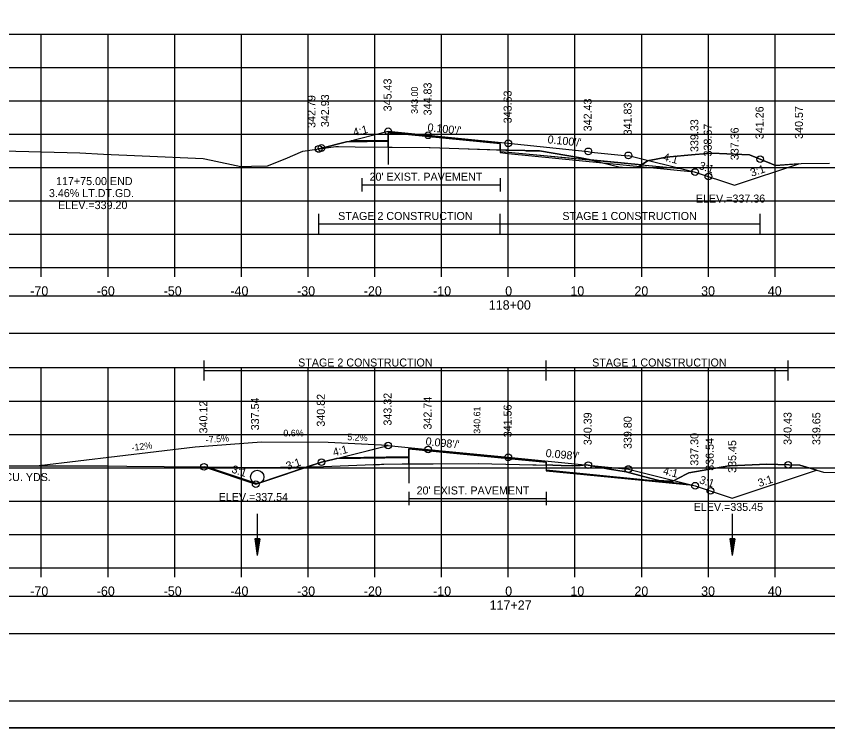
# Model space of a CAD drawing. Extents: x 1376273 to 1384221, y 378927 to 384592.
# Drawn here: x 1376984 to 1377105.7, y 380111.8 to 380218.5 of the extents above; entities that cross this region are included whole.
import ezdxf

# ---------------------------------------------------------------- set-up
doc = ezdxf.new("R2010")
doc.units = 0
for name, color, linetype in [('R_Alt Surface', 7, 'Continuous'), ('R_Axis', 7, 'Continuous'), ('R_Axis Annot', 7, 'Continuous'), ('R_Border', 7, 'Continuous'), ('R_Border Notes', 7, 'Continuous'), ('R_Dimension', 7, 'Continuous'), ('R_Drive', 7, 'Continuous'), ('R_Exist Surface', 7, 'Continuous'), ('R_Fin Surface', 7, 'Continuous'), ('R_Grid', 7, 'Continuous'), ('R_No Plot', 7, 'Continuous'), ('R_Water', 7, 'Continuous'), ('R_Xsect Elev', 7, 'Continuous'), ('R_Xsect Slope', 7, 'Continuous'), ('T_Detection Zones', 7, 'Continuous'), ('T_Notes', 7, 'Continuous'), ('T_Vehicle Path Lt Minor', 7, 'Continuous')]:
    doc.layers.add(name, color=color, linetype=linetype)

msp = doc.modelspace()

# ---------------------------------------------------------------- linework, layer by layer
at = {"layer": 'R_Alt Surface'}
for points in [[(1377034.2, 380199.86), (1377039.76, 380199.92), (1377039.77, 380201.08), (1377056.54, 380199.4), (1377056.54, 380198.24), (1377057.77, 380198.12), (1377083.58, 380195.7)], [(1377035.83, 380194.24), (1377035.83, 380192.24)], [(1377035.83, 380193.24), (1377056.54, 380193.24)], [(1377056.54, 380194.24), (1377056.54, 380192.24)], [(1377032.7, 380152.37), (1377042.87, 380152.5), (1377042.88, 380153.67), (1377057.77, 380152.21), (1377063.46, 380151.66), (1377063.47, 380150.49), (1377084.6, 380148.41)], [(1377042.88, 380147.2), (1377042.88, 380145.2)], [(1377063.46, 380147.2), (1377063.46, 380145.2)], [(1377042.88, 380146.2), (1377063.46, 380146.2)]]:
    msp.add_lwpolyline(points, dxfattribs=at)
at = {"layer": 'R_Axis'}
for p, q in [((1376907.77, 380180.82), (1377207.77, 380180.82)), ((1376987.77, 380179.42), (1376987.77, 380180.82)), ((1376997.77, 380179.42), (1376997.77, 380180.82)), ((1377007.77, 380179.42), (1377007.77, 380180.82)), ((1377017.77, 380179.42), (1377017.77, 380180.82)), ((1377027.77, 380179.42), (1377027.77, 380180.82)), ((1377037.77, 380179.42), (1377037.77, 380180.82)), ((1377047.77, 380179.42), (1377047.77, 380180.82)), ((1377057.77, 380179.42), (1377057.77, 380180.82)), ((1377067.77, 380179.42), (1377067.77, 380180.82)), ((1377077.77, 380179.42), (1377077.77, 380180.82)), ((1377087.77, 380179.42), (1377087.77, 380180.82)), ((1377097.77, 380179.42), (1377097.77, 380180.82)), ((1376907.77, 380135.82), (1377207.77, 380135.82)), ((1376987.77, 380134.42), (1376987.77, 380135.82)), ((1376997.77, 380134.42), (1376997.77, 380135.82)), ((1377007.77, 380134.42), (1377007.77, 380135.82)), ((1377017.77, 380134.42), (1377017.77, 380135.82)), ((1377027.77, 380134.42), (1377027.77, 380135.82)), ((1377037.77, 380134.42), (1377037.77, 380135.82)), ((1377047.77, 380134.42), (1377047.77, 380135.82)), ((1377057.77, 380134.42), (1377057.77, 380135.82)), ((1377067.77, 380134.42), (1377067.77, 380135.82)), ((1377077.77, 380134.42), (1377077.77, 380135.82)), ((1377087.77, 380134.42), (1377087.77, 380135.82)), ((1377097.77, 380134.42), (1377097.77, 380135.82))]:
    msp.add_line(p, q, dxfattribs=at)
at = {"layer": 'R_Axis Annot'}
for points in [[(1376907.2, 380171), (1377209.01, 380171), (1377209.01, 380176.52), (1376907.2, 380176.52)], [(1376907.2, 380125.98), (1377209.01, 380125.98), (1377209.01, 380131.5), (1376907.2, 380131.5)]]:
    msp.add_lwpolyline(points, close=True, dxfattribs=at)
at = {"layer": 'R_Border'}
msp.add_line((1377215.95, 380115.82), (1376899.77, 380115.82), dxfattribs=at)
at = {"layer": 'R_Dimension'}
for p, q in [((1377029.35, 380185.86), (1377029.35, 380188.86)), ((1377056.54, 380185.86), (1377056.54, 380188.86)), ((1377095.54, 380185.86), (1377095.54, 380188.86)), ((1377029.35, 380187.36), (1377095.54, 380187.36)), ((1377012.16, 380163.89), (1377012.16, 380166.89)), ((1377063.46, 380163.89), (1377063.46, 380166.89)), ((1377099.74, 380163.89), (1377099.74, 380166.89)), ((1377012.16, 380165.39), (1377099.74, 380165.39))]:
    msp.add_line(p, q, dxfattribs=at)
at = {"layer": 'R_Drive'}
for p, q in [((1377020.78, 380154.66), (1377010.81, 380153.91)), ((1377030.78, 380154.6), (1377020.78, 380154.66)), ((1377039.77, 380154.14), (1377030.78, 380154.6)), ((1377010.81, 380153.91), (1376987.46, 380151.1))]:
    msp.add_line(p, q, dxfattribs=at)
at = {"layer": 'R_Exist Surface'}
for points in [[(1376982.06, 380198.31), (1376993.54, 380198.01), (1376997.08, 380197.85), (1377002.89, 380197.6), (1377012.03, 380197.2), (1377013.25, 380196.95), (1377017.7, 380195.97), (1377019.28, 380196.02), (1377021.67, 380196.08), (1377024.33, 380197.12), (1377026.97, 380198.26), (1377030.82, 380198.83), (1377031.92, 380198.98), (1377032.34, 380198.97), (1377034.83, 380198.92), (1377045.89, 380198.82), (1377045.98, 380198.82), (1377046.06, 380198.81), (1377050.34, 380198.67), (1377057.41, 380198.44), (1377057.54, 380198.44), (1377057.58, 380198.44), (1377060.27, 380198.36), (1377060.47, 380198.35), (1377062.45, 380198.33), (1377068.6, 380197.26), (1377069.58, 380197.09), (1377069.89, 380197.01), (1377074.52, 380195.87), (1377074.89, 380195.86), (1377077.11, 380195.82), (1377077.97, 380196.39), (1377078.63, 380196.84), (1377079.93, 380197.08), (1377081.45, 380197.4), (1377085.77, 380197.8), (1377088.28, 380197.96), (1377092.8, 380197.76), (1377093.94, 380197.72), (1377097.21, 380196.4), (1377097.84, 380196.13), (1377101.66, 380196.41), (1377105.91, 380196.47)], [(1376977.69, 380151.12), (1376997.62, 380151.08), (1377000.57, 380151.06), (1377006.18, 380151), (1377021.89, 380150.85), (1377022.59, 380150.85), (1377023.6, 380150.91), (1377026.07, 380150.89), (1377030.06, 380150.98), (1377037.58, 380151.28), (1377038.46, 380151.32), (1377038.77, 380151.33), (1377038.8, 380151.33), (1377039.14, 380151.34), (1377041.88, 380151.41), (1377046.49, 380151.42), (1377053.28, 380151.43), (1377059.44, 380151.29), (1377064.46, 380151.18), (1377065.71, 380151.15), (1377067.41, 380151.1), (1377068.57, 380151.16), (1377069.48, 380151.23), (1377072.65, 380150.67), (1377075.46, 380150.18), (1377078.97, 380149.24), (1377080.32, 380148.89), (1377081.86, 380148.82), (1377082.44, 380148.8), (1377083.07, 380149.15), (1377084.83, 380150.05), (1377090.82, 380151.08), (1377090.94, 380151.1), (1377091.03, 380151.1), (1377096.53, 380151.37), (1377099.83, 380151.24), (1377101.49, 380151.19), (1377104.51, 380150.31), (1377105.03, 380150.14), (1377109.27, 380150.05)]]:
    msp.add_lwpolyline(points, dxfattribs=at)
at = {"layer": 'R_Fin Surface'}
for points in [[(1377029.35, 380198.61), (1377029.77, 380198.75), (1377033.53, 380199.69), (1377039.77, 380201.25), (1377045.77, 380200.65), (1377057.77, 380199.45), (1377069.77, 380198.25), (1377070.19, 380198.11), (1377075.68, 380197.56), (1377075.77, 380197.65), (1377085.64, 380195.18), (1377085.77, 380195.15), (1377091.7, 380193.17), (1377101.34, 380196.39), (1377101.34, 380196.39), (1377101.34, 380196.39)], [(1377012.16, 380150.94), (1377019.91, 380148.36), (1377029.77, 380151.64), (1377031.67, 380152.11), (1377039.77, 380154.14), (1377045.77, 380153.55), (1377057.77, 380152.38), (1377069.77, 380151.21), (1377075.77, 380150.62), (1377085.77, 380148.12), (1377091.34, 380146.26), (1377103.96, 380150.47)]]:
    msp.add_lwpolyline(points, dxfattribs=at)
at = {"layer": 'R_Grid'}
for p, q in [((1376907.77, 380215.82), (1377207.77, 380215.82)), ((1376907.77, 380215.82), (1377207.77, 380215.82)), ((1376987.77, 380180.82), (1376987.77, 380215.82)), ((1376987.77, 380180.82), (1376987.77, 380215.82)), ((1376997.77, 380180.82), (1376997.77, 380215.82)), ((1376997.77, 380180.82), (1376997.77, 380215.82)), ((1377007.77, 380180.82), (1377007.77, 380215.82)), ((1377007.77, 380180.82), (1377007.77, 380215.82)), ((1377017.77, 380180.82), (1377017.77, 380215.82)), ((1377017.77, 380180.82), (1377017.77, 380215.82)), ((1377027.77, 380180.82), (1377027.77, 380215.82)), ((1377027.77, 380180.82), (1377027.77, 380215.82)), ((1377037.77, 380180.82), (1377037.77, 380215.82)), ((1377037.77, 380180.82), (1377037.77, 380215.82)), ((1377047.77, 380180.82), (1377047.77, 380215.82)), ((1377047.77, 380180.82), (1377047.77, 380215.82)), ((1377057.77, 380180.82), (1377057.77, 380215.82)), ((1377057.77, 380180.82), (1377057.77, 380215.82)), ((1377067.77, 380180.82), (1377067.77, 380215.82)), ((1377067.77, 380180.82), (1377067.77, 380215.82)), ((1377077.77, 380180.82), (1377077.77, 380215.82)), ((1377077.77, 380180.82), (1377077.77, 380215.82)), ((1377087.77, 380180.82), (1377087.77, 380215.82)), ((1377087.77, 380180.82), (1377087.77, 380215.82)), ((1377097.77, 380180.82), (1377097.77, 380215.82)), ((1377097.77, 380180.82), (1377097.77, 380215.82)), ((1376907.77, 380210.82), (1377207.77, 380210.82)), ((1376907.77, 380210.82), (1377207.77, 380210.82)), ((1376907.77, 380205.82), (1377207.77, 380205.82)), ((1376907.77, 380205.82), (1377207.77, 380205.82)), ((1376907.77, 380200.82), (1377207.77, 380200.82)), ((1376907.77, 380200.82), (1377207.77, 380200.82)), ((1376907.77, 380195.82), (1377207.77, 380195.82)), ((1376907.77, 380195.82), (1377207.77, 380195.82)), ((1376907.77, 380190.82), (1377207.77, 380190.82)), ((1376907.77, 380190.82), (1377207.77, 380190.82)), ((1376907.77, 380185.82), (1377207.77, 380185.82)), ((1376907.77, 380185.82), (1377207.77, 380185.82)), ((1376907.77, 380180.82), (1377207.77, 380180.82)), ((1376907.77, 380180.82), (1377207.77, 380180.82)), ((1376907.77, 380165.82), (1377207.77, 380165.82)), ((1376907.77, 380165.82), (1377207.77, 380165.82)), ((1376987.77, 380135.82), (1376987.77, 380165.82)), ((1376987.77, 380135.82), (1376987.77, 380165.82)), ((1376997.77, 380135.82), (1376997.77, 380165.82)), ((1376997.77, 380135.82), (1376997.77, 380165.82)), ((1377007.77, 380135.82), (1377007.77, 380165.82)), ((1377007.77, 380135.82), (1377007.77, 380165.82)), ((1377017.77, 380135.82), (1377017.77, 380165.82)), ((1377017.77, 380135.82), (1377017.77, 380165.82)), ((1377027.77, 380135.82), (1377027.77, 380165.82)), ((1377027.77, 380135.82), (1377027.77, 380165.82)), ((1377037.77, 380135.82), (1377037.77, 380165.82)), ((1377037.77, 380135.82), (1377037.77, 380165.82)), ((1377047.77, 380135.82), (1377047.77, 380165.82)), ((1377047.77, 380135.82), (1377047.77, 380165.82)), ((1377057.77, 380135.82), (1377057.77, 380165.82)), ((1377057.77, 380135.82), (1377057.77, 380165.82)), ((1377067.77, 380135.82), (1377067.77, 380165.82)), ((1377067.77, 380135.82), (1377067.77, 380165.82)), ((1377077.77, 380135.82), (1377077.77, 380165.82)), ((1377077.77, 380135.82), (1377077.77, 380165.82)), ((1377087.77, 380135.82), (1377087.77, 380165.82)), ((1377087.77, 380135.82), (1377087.77, 380165.82)), ((1377097.77, 380135.82), (1377097.77, 380165.82)), ((1377097.77, 380135.82), (1377097.77, 380165.82)), ((1376907.77, 380160.82), (1377207.77, 380160.82)), ((1376907.77, 380160.82), (1377207.77, 380160.82)), ((1376907.77, 380155.82), (1377207.77, 380155.82)), ((1376907.77, 380155.82), (1377207.77, 380155.82)), ((1376907.77, 380150.82), (1377207.77, 380150.82)), ((1376907.77, 380150.82), (1377207.77, 380150.82)), ((1376907.77, 380145.82), (1377207.77, 380145.82)), ((1376907.77, 380145.82), (1377207.77, 380145.82)), ((1376907.77, 380140.82), (1377207.77, 380140.82)), ((1376907.77, 380140.82), (1377207.77, 380140.82)), ((1376907.77, 380135.82), (1377207.77, 380135.82)), ((1376907.77, 380135.82), (1377207.77, 380135.82))]:
    msp.add_line(p, q, dxfattribs=at)
at = {"layer": 'R_No Plot'}
msp.add_line((1376887.37, 380111.84), (1377220.7, 380111.84), dxfattribs=at)
for points in [[(1376887.36, 380325.17), (1377220.7, 380325.17), (1377220.7, 380111.84), (1376887.36, 380111.84)], [(1377133.69, 380321.28), (1377133.69, 380311.4), (1377169.42, 380311.4), (1377169.42, 380308.48), (1377192.62, 380308.48), (1377192.62, 380284.15), (1377215.95, 380284.15), (1377215.95, 380115.82), (1376899.77, 380115.82), (1376899.77, 380321.28)]]:
    msp.add_lwpolyline(points, close=True, dxfattribs=at)
for points in [[(1377033.53, 380199.69), (1377039.76, 380199.75), (1377039.77, 380201.08), (1377056.54, 380199.4), (1377056.54, 380198.07), (1377057.77, 380197.95), (1377085.64, 380195.18)], [(1377032.03, 380152.21), (1377042.87, 380152.34), (1377042.88, 380153.67), (1377057.77, 380152.21), (1377063.46, 380151.66), (1377063.47, 380150.33), (1377085.51, 380148.19)]]:
    msp.add_lwpolyline(points, dxfattribs=at)
for centre in [(1377039.77, 380201.25), (1377039.77, 380201.25), (1377045.77, 380200.65), (1377045.77, 380200.65), (1377029.77, 380198.75), (1377029.77, 380198.75), (1377057.77, 380199.45), (1377057.77, 380199.45), (1377029.35, 380198.61), (1377029.35, 380198.61), (1377069.77, 380198.25), (1377069.77, 380198.25), (1377075.77, 380197.65), (1377075.77, 380197.65), (1377095.54, 380197.08), (1377095.54, 380197.08), (1377085.77, 380195.15), (1377085.77, 380195.15), (1377087.77, 380194.48), (1377087.77, 380194.48), (1377087.77, 380194.48), (1377087.77, 380194.48), (1377039.77, 380154.14), (1377039.77, 380154.14), (1377045.77, 380153.55), (1377045.77, 380153.55), (1377029.77, 380151.64), (1377029.77, 380151.64), (1377057.77, 380152.38), (1377057.77, 380152.38), (1377069.77, 380151.21), (1377069.77, 380151.21), (1377099.74, 380151.25), (1377099.74, 380151.25), (1377012.16, 380150.94), (1377012.16, 380150.94), (1377075.77, 380150.62), (1377075.77, 380150.62), (1377019.91, 380148.36), (1377019.91, 380148.36), (1377019.91, 380148.36), (1377019.91, 380148.36), (1377085.77, 380148.12), (1377085.77, 380148.12), (1377088.07, 380147.36), (1377088.07, 380147.36), (1377088.07, 380147.36), (1377088.07, 380147.36)]:
    msp.add_circle(centre, 0.5, dxfattribs=at)
at = {"layer": 'R_Water'}
for p, q in [((1377020.14, 380143.91), (1377020.14, 380137.66)), ((1377091.34, 380143.91), (1377091.34, 380137.66)), ((1377019.76, 380140.16), (1377020.14, 380137.66)), ((1377020.51, 380140.16), (1377019.76, 380140.16)), ((1377019.82, 380140.16), (1377020.14, 380138.08)), ((1377019.89, 380140.16), (1377020.14, 380138.51)), ((1377019.95, 380140.16), (1377020.14, 380138.93)), ((1377020.01, 380140.16), (1377020.14, 380139.35)), ((1377020.08, 380140.16), (1377020.14, 380139.77)), ((1377020.51, 380140.16), (1377020.14, 380137.66)), ((1377020.26, 380140.16), (1377020.14, 380139.35)), ((1377020.39, 380140.16), (1377020.14, 380138.51)), ((1377020.45, 380140.16), (1377020.14, 380138.08)), ((1377020.32, 380140.16), (1377020.14, 380138.93)), ((1377020.2, 380140.16), (1377020.14, 380139.77)), ((1377090.97, 380140.16), (1377091.34, 380137.66)), ((1377091.72, 380140.16), (1377090.97, 380140.16)), ((1377091.03, 380140.16), (1377091.34, 380138.08)), ((1377091.1, 380140.16), (1377091.34, 380138.51)), ((1377091.16, 380140.16), (1377091.34, 380138.93)), ((1377091.22, 380140.16), (1377091.34, 380139.35)), ((1377091.29, 380140.16), (1377091.34, 380139.77)), ((1377091.72, 380140.16), (1377091.34, 380137.66)), ((1377091.47, 380140.16), (1377091.34, 380139.35)), ((1377091.59, 380140.16), (1377091.34, 380138.51)), ((1377091.66, 380140.16), (1377091.34, 380138.08)), ((1377091.53, 380140.16), (1377091.34, 380138.93)), ((1377091.4, 380140.16), (1377091.34, 380139.77))]:
    msp.add_line(p, q, dxfattribs=at)
msp.add_circle((1377020.14, 380149.43), 1, dxfattribs=at)
at = {"layer": 'T_Detection Zones'}
for p, q in [((1377039.76, 380199.75), (1377033.53, 380199.69)), ((1377039.76, 380199.75), (1377039.76, 380196.3)), ((1377039.76, 380198.88), (1377039.76, 380199.75)), ((1377056.54, 380198.47), (1377056.54, 380198.24)), ((1377077.74, 380196.25), (1377070.08, 380196.97)), ((1377077.74, 380196.25), (1377083.58, 380195.7)), ((1377083.58, 380195.7), (1377085.64, 380195.18)), ((1377042.87, 380152.34), (1377032.03, 380152.21)), ((1377042.87, 380152.34), (1377042.87, 380148.48)), ((1377042.87, 380151.41), (1377042.87, 380152.34)), ((1377063.46, 380151.2), (1377063.47, 380150.49)), ((1377063.47, 380150.49), (1377084.6, 380148.41))]:
    msp.add_line(p, q, dxfattribs=at)
for points in [[(1377033.53, 380199.69), (1377029.77, 380198.75), (1377029.35, 380198.61)], [(1377029.35, 380198.61), (1377030.82, 380198.83), (1377031.92, 380198.98), (1377032.34, 380198.97), (1377034.83, 380198.92), (1377039.76, 380198.88)], [(1377070.08, 380196.97), (1377069.89, 380197.01), (1377069.58, 380197.09), (1377068.6, 380197.26), (1377062.45, 380198.33), (1377060.47, 380198.35), (1377060.27, 380198.36), (1377057.58, 380198.44), (1377057.54, 380198.44), (1377057.41, 380198.44), (1377056.54, 380198.47)], [(1377056.54, 380198.24), (1377057.77, 380198.12), (1377070.08, 380196.97)], [(1377101.34, 380196.39), (1377097.84, 380196.13), (1377097.21, 380196.4), (1377093.94, 380197.72), (1377092.8, 380197.76), (1377088.28, 380197.96), (1377085.77, 380197.8), (1377081.45, 380197.4), (1377079.93, 380197.08), (1377078.85, 380196.88), (1377078.63, 380196.84), (1377077.97, 380196.39), (1377077.74, 380196.25)], [(1377070.08, 380196.97), (1377074.52, 380195.87), (1377074.89, 380195.86), (1377077.11, 380195.82), (1377077.74, 380196.25)], [(1377085.64, 380195.18), (1377085.77, 380195.15), (1377091.7, 380193.17), (1377101.34, 380196.39)], [(1377032.03, 380152.21), (1377031.67, 380152.11), (1377029.77, 380151.64), (1377027.63, 380150.93)], [(1377027.63, 380150.93), (1377030.06, 380150.98), (1377037.58, 380151.28), (1377038.46, 380151.32), (1377038.77, 380151.33), (1377038.8, 380151.33), (1377039.14, 380151.34), (1377041.88, 380151.41), (1377042.87, 380151.41)], [(1377103.96, 380150.47), (1377101.49, 380151.19), (1377099.83, 380151.24), (1377096.53, 380151.37), (1377091.03, 380151.1), (1377090.94, 380151.1), (1377090.82, 380151.08), (1377084.83, 380150.05), (1377083.07, 380149.15), (1377082.63, 380148.91), (1377082.44, 380148.8), (1377081.86, 380148.82), (1377080.32, 380148.89), (1377078.97, 380149.24), (1377075.46, 380150.18), (1377072.65, 380150.67), (1377069.48, 380151.23), (1377068.57, 380151.16), (1377067.41, 380151.1), (1377065.71, 380151.15), (1377064.46, 380151.18), (1377063.46, 380151.2)], [(1377084.6, 380148.41), (1377085.77, 380148.12), (1377091.34, 380146.26), (1377103.96, 380150.47)]]:
    msp.add_lwpolyline(points, dxfattribs=at)
msp.add_lwpolyline([(1377012.16, 380150.94), (1377021.89, 380150.85), (1377022.59, 380150.85), (1377023.6, 380150.91), (1377026.07, 380150.89), (1377027.63, 380150.93), (1377019.91, 380148.36)], close=True, dxfattribs=at)
at = {"layer": 'T_Notes'}
for p, q in [((1377020.78, 380154.66), (1377010.81, 380153.91)), ((1377030.78, 380154.6), (1377020.78, 380154.66)), ((1377039.77, 380154.14), (1377030.78, 380154.6)), ((1377010.81, 380153.91), (1376987.46, 380151.1))]:
    msp.add_line(p, q, dxfattribs=at)
for points in [[(1377029.77, 380151.64), (1377033.21, 380152.5), (1377039.77, 380154.14)], [(1376987.46, 380151.1), (1376997.62, 380151.08), (1377000.57, 380151.06), (1377006.18, 380151), (1377012.62, 380150.94)], [(1377012.62, 380150.94), (1377020.14, 380148.43), (1377027.63, 380150.93), (1377029.77, 380151.64)]]:
    msp.add_lwpolyline(points, dxfattribs=at)
at = {"layer": 'T_Vehicle Path Lt Minor'}
for p, q in [((1377039.76, 380199.75), (1377039.76, 380198.88)), ((1377056.54, 380198.47), (1377056.54, 380199.4)), ((1377042.87, 380152.34), (1377042.87, 380151.41)), ((1377063.46, 380151.2), (1377063.46, 380151.66))]:
    msp.add_line(p, q, dxfattribs=at)
for points in [[(1377056.54, 380199.4), (1377039.77, 380201.08), (1377039.76, 380199.75)], [(1377039.76, 380198.88), (1377045.89, 380198.82), (1377045.98, 380198.82), (1377046.06, 380198.81), (1377050.34, 380198.67), (1377056.54, 380198.47)], [(1377063.46, 380151.66), (1377057.77, 380152.21), (1377042.88, 380153.67), (1377042.87, 380152.34)], [(1377042.87, 380151.41), (1377046.49, 380151.42), (1377053.28, 380151.43), (1377059.44, 380151.29), (1377063.46, 380151.2)]]:
    msp.add_lwpolyline(points, dxfattribs=at)

# ---------------------------------------------------------------- texts
at = {"layer": 'R_Alt Surface'}
for p in [(1377036.98, 380193.85), (1377044.03, 380146.81)]:
    msp.add_text("20' EXIST. PAVEMENT", height=1.2, dxfattribs=at).set_placement(p)
at = {"layer": 'R_Axis Annot'}
for s, p in [('-70', (1376986.11, 380176.62)), ('-60', (1376996.08, 380176.62)), ('-50', (1377006.11, 380176.62)), ('-40', (1377016.11, 380176.62)), ('-30', (1377026.11, 380176.62)), ('-20', (1377036.11, 380176.62)), ('-10', (1377046.5, 380176.62)), ('0', (1377057.31, 380176.62)), ('10', (1377067.08, 380176.62)), ('20', (1377076.68, 380176.62)), ('30', (1377086.68, 380176.62)), ('40', (1377096.68, 380176.62)), ('118+00', (1377054.85, 380174.52)), ('-70', (1376986.11, 380131.62)), ('-60', (1376996.08, 380131.62)), ('-50', (1377006.11, 380131.62)), ('-40', (1377016.11, 380131.62)), ('-30', (1377026.11, 380131.62)), ('-20', (1377036.11, 380131.62)), ('-10', (1377046.5, 380131.62)), ('0', (1377057.31, 380131.62)), ('10', (1377067.08, 380131.62)), ('20', (1377076.68, 380131.62)), ('30', (1377086.68, 380131.62)), ('40', (1377096.68, 380131.62)), ('117+27', (1377054.97, 380129.52))]:
    msp.add_text(s, height=1.4, dxfattribs=at).set_placement(p)
at = {"layer": 'R_Border Notes'}
for s, p in [('ELEV.=337.36', (1377085.89, 380190.57)), ('ELEV.=337.54', (1377014.36, 380145.83)), ('ELEV.=335.45', (1377085.57, 380144.34))]:
    msp.add_text(s, height=1.2, dxfattribs=at).set_placement(p)
at = {"layer": 'R_Dimension'}
for s, p in [('STAGE 2 CONSTRUCTION', (1377032.27, 380187.96)), ('STAGE 1 CONSTRUCTION', (1377065.88, 380187.96)), ('STAGE 2 CONSTRUCTION', (1377026.27, 380165.99)), ('STAGE 1 CONSTRUCTION', (1377070.35, 380165.99))]:
    msp.add_text(s, height=1.2, dxfattribs=at).set_placement(p)
at = {"layer": 'R_Drive'}
for s, rotation, p in [('-7.5%', 4.2611, (1377012.45, 380154.51)), ('0.6%', 359.6871, (1377024.05, 380155.52)), ('5.2%', 357.0531, (1377033.62, 380154.96)), ('-12%', 6.868, (1377001.35, 380153.33))]:
    msp.add_text(s, height=1, rotation=rotation, dxfattribs=at).set_placement(p)
msp.add_text('CONSTRUCT APPROACH = 134 CU. YDS.', height=1.2, dxfattribs=at).set_placement((1376957.76, 380148.82))
at = {"layer": 'R_No Plot'}
for s, p in [('341.26', (1377096.04, 380200.08)), ('338.67', (1377088.27, 380197.48)), ('340.43', (1377100.24, 380154.25)), ('336.54', (1377088.57, 380150.36))]:
    msp.add_text(s, height=1.2, rotation=90, dxfattribs=at).set_placement(p)
at = {"layer": 'R_Xsect Elev'}
for s, height, rotation, p in [('345.43', 1.2, 90, (1377040.27, 380204.25)), ('343.00', 1, 90, (1377044.22, 380203.87)), ('344.83', 1.2, 90, (1377046.27, 380203.65)), ('342.79', 1.2, 90, (1377028.86, 380201.76)), ('342.93', 1.2, 90, (1377030.9, 380201.88)), ('343.63', 1.2, 90, (1377058.27, 380202.45)), ('342.43', 1.2, 90, (1377070.27, 380201.25)), ('341.83', 1.2, 90, (1377076.27, 380200.65)), ('340.57', 1.2, 90, (1377101.94, 380200.12)), ('339.33', 1.2, 90, (1377086.27, 380198.15)), ('337.36', 1.2, 90, (1377092.3, 380196.92)), ('117+75.00 END', 1.2, 360, (1376989.98, 380193.19)), ('3.46% LT.DT.GD.', 1.2, 360, (1376988.91, 380191.39)), ('ELEV.=339.20', 1.2, 360, (1376990.28, 380189.59)), ('340.82', 1.2, 90, (1377030.27, 380156.98)), ('343.32', 1.2, 90, (1377040.27, 380157.14)), ('340.12', 1.2, 90, (1377012.66, 380155.96)), ('337.54', 1.2, 90, (1377020.41, 380156.43)), ('342.74', 1.2, 90, (1377046.27, 380156.55)), ('341.56', 1.2, 90, (1377058.27, 380155.38)), ('340.61', 1, 90, (1377053.58, 380155.91)), ('340.39', 1.2, 90, (1377070.27, 380154.21)), ('339.65', 1.2, 90, (1377104.56, 380154.22)), ('339.80', 1.2, 90, (1377076.27, 380153.62)), ('337.30', 1.2, 90, (1377086.27, 380151.12)), ('335.45', 1.2, 90, (1377091.94, 380150.05))]:
    msp.add_text(s, height=height, rotation=rotation, dxfattribs=at).set_placement(p)
at = {"layer": 'R_Xsect Slope'}
for s, rotation, p in [('4:1', 14.0362, (1377034.65, 380200.49)), ("0.100'/'", 354.2894, (1377045.62, 380201.27)), ("0.100'/'", 354.2894, (1377063.62, 380199.47)), ('4:1', 345.9638, (1377080.89, 380196.89)), ('3:1', 341.5651, (1377086.24, 380195.64)), ('3:1', 18.4349, (1377094.27, 380194.43)), ("0.098'/'", 354.4191, (1377045.33, 380154.2)), ('4:1', 14.0362, (1377031.63, 380152.52)), ("0.098'/'", 354.4191, (1377063.33, 380152.44)), ('3:1', 18.4349, (1377024.68, 380150.47)), ('3:1', 341.5651, (1377016.2, 380150.12)), ('4:1', 345.9638, (1377080.89, 380149.86)), ('3:1', 341.5651, (1377086.31, 380148.53)), ('3:1', 18.4349, (1377095.41, 380147.91))]:
    msp.add_text(s, height=1.2, rotation=rotation, dxfattribs=at).set_placement(p)

doc.saveas('drawing.dxf')
